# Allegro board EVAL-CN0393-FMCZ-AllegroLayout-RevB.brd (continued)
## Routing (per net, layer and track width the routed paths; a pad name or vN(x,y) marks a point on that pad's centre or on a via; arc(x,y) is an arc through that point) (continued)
VDD: length 13.1
  TOP w0.2: U1.19 28.75,16.12
  TOP w0.25: U2.20 28.25,44.25 28.75,44.25 U2.19 ; v1(28.75,16.88) 28.75,16.12 28.38,16.12 28.25,16 U1.20
  TOP w0.3: 28.75,44.25 v1(28.75,44.88)
  TOP w0.5: R54.1 v1(29.88,45.5) ; R53.1 v1(29.75,17.5) ; v1(28.75,44.88) C47.1 ; v1(28.75,16.88) C46.1
  LAYER3 w0.2: VDD.1 33.31,51.75 ; VDD.1 31.19,51.75 ; VDD.1 32.25,50.69 ; VDD.1 32.25,52.81
  BOTTOM w0.5: C30.1 v1(28.75,16.88) ; C31.1 v1(28.75,44.88)
VDD2: length 8
  TOP w0.3: C7.1 47.25,43.5 47.38,43.62 U6.18
  TOP w0.5: C12.2 v1(46.5,26.62) ; C7.1 v1(45.75,43.5)
  LAYER3 w0.2: VDD2.1 45.81,25 ; VDD2.1 44.75,23.94 ; VDD2.1 43.69,25 ; VDD2.1 44.75,26.06
  vias: v1(45.75,44) v1(47.62,27.62) v1(47.62,26.88) v1(48.38,27.62) v1(48.38,26.88)
VDDA: length 15.7
  TOP w0.37: v1(57.5,48.25) 57.5,47.95 57.08,47.52 U6.9
  TOP w1: v2(61.62,49.5) R35.2
  BOTTOM w0.5: v1(57.5,48.25) 58.75,49.5 v2(61.62,49.5)
  BOTTOM w1.5: v2(61.62,49.5) 61.62,50.96 60.5,52.08 VDDA.1
+ISO: length 5.9
  TOP w0.25: U6.20 48.69,41.68 ; 48.69,41.68 48.69,41.55 ; 48.69,41.68 v1(48.62,41.75)
  LAYER3 w0.2: UNK+ISO.1 39.81,65.25 ; UNK+ISO.1 38.75,64.19 ; UNK+ISO.1 38.75,66.31 ; UNK+ISO.1 37.69,65.25
  BOTTOM w0.5: v1(48.62,41.75) 48.75,41.88 R5.1
  vias: v1(48,41.75) v1(48,41) v1(48.75,41) v1(49.38,41.75) v1(49.38,41)
+VS: length 9.9
  TOP w0.25: C53.1 v1(15.5,45) A2.8 ; A1.8 v1(15.38,16.62) C52.1
  LAYER3 w0.2: UNK+VS.1 27.25,66.56 ; UNK+VS.1 27.25,64.44 ; UNK+VS.1 28.31,65.5 ; UNK+VS.1 26.19,65.5
  BOTTOM w0.25: C36.1 v1(15.5,45) ; C35.1 v1(15.38,16.62)
-ISO: length 4.8
  TOP w1: R8.2 UNK-ISO.1
  BOTTOM w1: R11.1 42.5,47.5 UNK-ISO.1
-VS: length 35.6
  TOP w0.25: C54.1 v1(15.38,9.88) A1.3 ; A2.6 16.95,43.67 ; C55.1 v1(15.5,38) A2.3 ; A1.6 16.83,15.55
  TOP w0.3: 16.83,15.55 v1(16.88,15.5) ; 16.95,43.67 v1(17,43.62)
  TOP w0.75: v2(36.5,34.62) 36.5,33.54 35.46,32.5 16.12,32.5 14.25,34.38 14.25,36.62 14.88,37.25 C55.1
  BOTTOM w0.25: C37.1 v1(15.38,9.88) ; C38.1 v1(15.5,38)
  BOTTOM w0.3: R22.1 36.5,33.85 v2(36.5,34.62)
AMP_OUTA: length 9.4
  TOP w0.25: U1.3 24.13,13.75 C65.2
  TOP w0.4: C65.2 23.53,13.15 RN1.8 ; 22.55,11.36 23.12,10.79 AMP_A.1 ; 22.55,11.36 22.5,11.41 v1(22.5,11.62) ; 22.55,11.36 RN1.8 ; RN1.8 RN1.7
  BOTTOM w0.4: CR1.3 22.38,11.75 v1(22.5,11.62)
AMP_OUTB: length 9.2
  TOP w0.25: C66.2 24.13,41.75 U2.3
  TOP w0.4: RN2.8 23.02,41.49 C66.2 ; RN2.8 22.68,40.24 22.88,40.04 v1(22.88,39.38) AMP_B.1 ; RN2.8 RN2.7
  BOTTOM w0.4: v1(22.88,39.38) 23.38,39.88 CR2.3
CA+: length 38.2
  TOP w0.4: R47.1 11,20.64 10.9,20.74 10.9,20.95 10.32,21.54 D6.2 8.7,21.54 8.66,21.5 CA+.1 J1.1
  BOTTOM w0.4: P2.3 9,45.17 9,30 8.5,29.5 8.5,27 7.5,26 CA+.1
CA-: length 37.5
  TOP w0.4: R48.1 10.75,8.86 D7.1 9.37,8.46 8.66,7.75 CA-.1 J2.1
  BOTTOM w0.4: P3.1 6.25,31.75 6.25,14.25 7.5,13 CA-.1
CB+: length 9.6
  TOP w0.4: J3.1 2.67,55.12 2.8,55.25 CB+.1 P2.1
CB-: length 9.6
  TOP w0.4: J4.1 6.21,41.38 6.34,41.5 CB-.1 P3.3
CNV: length 60.7
  TOP w0.2: U7.15 46.7,31.57 46.58,31.69 46.58,32.13 46.47,32.25 46.3,32.25 46.18,32.13 46.18,31.69 46.07,31.57 45.9,31.57 45.78,31.69 45.78,32.13 45.67,32.25 45.5,32.25 45.38,32.13 45.38,31.69 45.27,31.57 45.1,31.57 44.98,31.69 44.98,32.13 44.87,32.25 44.7,32.25 44.58,32.13 44.58,31.69 44.47,31.57 42.01,31.57 41.56,31.12 CNV.1 ; v1(32.12,12.25) 31.42,12.25 30.92,12.75 U1.13 ; U2.13 33.88,40.75 37.25,37.38 41.38,37.38 41.88,37.88 v1(41.88,39.25)
  BOTTOM w0.2: v1(32.12,12.25) 32.52,12.64 32.52,12.77 39,19.25 39,20.62 39.38,21 39.38,30 CNV.1 41.75,32.38 41.75,35 42.75,36 42.75,38.38 v1(41.88,39.25)
DCLK: length 23.2
  TOP w0.2: DCLK.1 64.5,24.75 61.75,24.75 61,25.5 61,30 57.47,33.52 U7.9
  BOTTOM w0.2: P1.H29 69.05,23.7 DCLK.1
G0A_ISO: length 73.5
  TOP w0.2: v1(41.54,6.71) 39.82,5 ADR0_A.1 38.5,5.25 ; U6.15 45.57,45.58 44.7,44.7 44.7,36.33 v1(42.75,34.38)
  TOP w0.25: A1.4 15.88,10.25 16,10.12 16,9.88 19,6.88 36.62,6.88 ADR0_A.1
  BOTTOM w0.2: v1(42.75,34.38) 42.36,33.98 42.36,10.11 41.54,9.29 v1(41.54,6.71)
G0B_ISO: length 44.3
  TOP w0.2: U6.13 45.67,46.88 43.8,45 43.8,38.17 42.12,36.5 34.25,36.5 ADR0_B.1 31.25,36 18.12,36 16.12,38 16.12,38.24 16,38.37 A2.4
G1A_ISO: length 69.6
  TOP w0.2: U6.16 45.55,44.92 45.12,44.5 45.12,35.5 v1(43.12,33.5) ; ADR1_A.1 v1(42.88,8.5)
  TOP w0.25: ADR1_A.1 37.62,7.62 19,7.62 16.5,10.12 16.5,10.38 16.38,10.5 A1.5
  BOTTOM w0.2: v1(43.12,33.5) 43.12,9.3 42.88,9.05 v1(42.88,8.5)
G1B_ISO: length 45.7
  TOP w0.2: v1(16.75,35.25) 17.75,34.25 ADR1_B.1 34.06,34.25 35.81,36 42.62,36 44.25,37.62 44.25,44.85 45.62,46.23 U6.14 ; v1(16.75,38.35) 16.5,38.6 A2.5
  BOTTOM w0.2: v1(16.75,35.25) v1(16.75,38.35)
GA0: length 21.2
  TOP w0.2: U19.1 67.47,5.09 68,5.62 68,9.38 69.5,10.88 69.5,11.5 69.75,11.75 70.38,11.75 74.12,15.5 75.38,15.5 77.25,17.38 v1(77.88,17.38)
  BOTTOM w0.2: P1.C34 77.19,17.38 v1(77.88,17.38)
GA1: length 16.8
  TOP w0.2: U19.2 66.86,6.37 67.5,7.01 67.5,9.75 69,11.25 69,11.75 69.75,12.5 70.38,12.5 74,16.12 v1(75.12,16.12)
  BOTTOM w0.2: P1.D35 75.86,16.12 v1(75.12,16.12)
GAIN_0A: length 17.6
  TOP w0.2: R46.1 v1(67.25,50.5) R44.1 ; U6.6 v1(57.08,45.58)
  BOTTOM w0.2: v1(57.08,45.58) 66.33,45.58 68.25,47.5 68.25,49.5 v1(67.25,50.5)
GAIN_0B: length 12.9
  TOP w0.2: R42.1 R40.1 66.75,48.24 v1(66.75,47.5) ; U6.8 v1(57.08,46.88)
  BOTTOM w0.2: v1(66.75,47.5) 66.12,46.88 v1(57.08,46.88)
GAIN_1A: length 19.8
  TOP w0.2: R45.1 v1(67.25,51.5) R43.2 ; U6.5 v1(57.5,44.92)
  BOTTOM w0.2: v1(67.25,51.5) 68.75,50 68.75,47.25 66.42,44.92 v1(57.5,44.92)
GAIN_1B: length 15.3
  TOP w0.2: R39.2 v1(67.25,49.25) R41.1 ; U6.7 v1(57.5,46.23)
  BOTTOM w0.2: v1(57.5,46.23) 66.35,46.23 67.75,47.62 67.75,48.75 v1(67.25,49.25)
IN_A: length 5.3
  TOP w0.4: IN_A.1 19.88,10.79 19.95,10.86 RN1.5 19.19,13.15 19.09,13.25 R51.2
IN_B: length 4.3
  TOP w0.4: R52.2 19.22,41.25 19.32,41.15 RN2.5 20.07,38.99 20,38.91 IN_B.1
MCLK: length 25
  TOP w0.2: U7.3 58.38,29.62 59,29 59,21.75 61.25,19.5 MCLK.1
  BOTTOM w0.2: MCLK.1 63.5,18.75 63.5,18.5 64.5,17.5 66.75,17.5 68.17,16.09 P1.H35
MISO: length 22.4
  TOP w0.2: MISO.1 61.69,23 60,24.69 60,29.5 58.58,30.93 U7.5
  BOTTOM w0.2: MISO.1 64.5,21.25 66.75,21.25 68.11,19.89 P1.H32
MOSI: length 24.2
  TOP w0.2: U7.4 58.47,30.27 59.5,29.25 59.5,22.75 60.75,21.5 63,21.5 65,19.5 MOSI.1
  BOTTOM w0.2: MOSI.1 68.39,17.36 P1.H34
MSS: length 22
  TOP w0.2: MSS.1 65,24.25 61.5,24.25 60.5,25.25 60.5,29.75 58.67,31.57 U7.6
  BOTTOM w0.2: MSS.1 68.08,21.16 P1.H31
Net_22: length 0
  BOTTOM w0.2: 77.17,32.59 77.2,32.62
REF_OUTA: length 3.5
  TOP w0.25: U1.24 26.25,15.7 25.8,15.7
  TOP w0.3: 25.8,15.7 v1(25.75,15.75)
  BOTTOM w0.3: v1(25.75,15.75) 25.12,15.12 25.06,15.12 25.05,15.12 24.3,15.12 24.17,14.99 CR1.2
REF_OUTB: length 2.6
  TOP w0.25: v1(25.8,43.8) 25.8,43.75 25.85,43.7 26.25,43.7 U2.24
  BOTTOM w0.25: v1(25.8,43.8) 25.12,43.12 24.56,43.12 CR2.2
SCK: length 61
  TOP w0.2: v1(38.12,38.62) 37.45,38.62 34.32,41.75 U2.15 ; v1(40.5,11.12) 39.75,11.12 37.12,13.75 U1.15 ; v1(38.25,26.75) SCK.1 43.25,27.25 43.25,28.5 44.75,30 47,30 47.38,29.62 U7.18
  BOTTOM w0.2: v1(38.12,38.62) 38.12,27.43 38.25,27.3 v1(38.25,26.75) ; v1(40.5,11.12) SCK.1
SDI_A: length 22.1
  TOP w0.2: v1(41.5,18.25) JP1.1 ; U7.17 47.47,30.27 47.25,30.5 44.31,30.5 41.56,27.75 SDIA.1
  BOTTOM w0.2: SDIA.1 41.75,26.5 41.75,19.18 41.5,18.93 v1(41.5,18.25)
SDO_A: length 34.7
  TOP w0.2: v1(38.75,39.62) 37.5,40.88 JP2.1 ; U1.14 31.33,13.25 31.38,13.2 v1(31.38,13.12)
  BOTTOM w0.2: v1(31.38,13.12) 37.5,19.25 SDOA.1 38.88,23.12 38.88,27 38.75,27.12 v1(38.75,39.62)
SDO_B: length 35.9
  TOP w0.2: U7.16 42.42,30.93 41.38,29.88 39.62,29.88 39.12,30.38 39.12,30.77 39.01,30.88 38.12,30.88 38,31 38,31.17 38.12,31.28 39.01,31.28 39.12,31.4 39.12,31.57 39.01,31.68 38.12,31.68 38,31.8 38,31.97 38.12,32.08 39.01,32.08 39.12,32.2 39.12,32.37 39.01,32.48 38.12,32.48 38,32.6 38,32.77 38.12,32.88 39.01,32.88 SDOB.1 ; U2.14 34.12,41.25 37.38,38 v1(39.88,38)
  BOTTOM w0.2: SDOB.1 40.5,35.75 39.88,36.38 v1(39.88,38)
UNNAMED_2_ADR45XX_I73_NC4: length 2
  TOP w0.75: U5.7 v1(14.88,55.62)
  BOTTOM w0.75: v1(14.88,55.62) 14.99,55.5 R2.1
UNNAMED_2_ADR45XX_I73_VOUT: length 3.4
  TOP w0.75: U5.6 14.76,56.88 v1(14.75,56.88) 13.88,56.88 R3.1
  BOTTOM w0.75: C5.1 15.12,57.25 v1(14.75,56.88)
UNNAMED_2_ADUM3470_I1_FB: length 3.2
  TOP w0.2: v1(47.5,44.25) 47.53,44.27 U6.17
  BOTTOM w0.5: 47.5,44 v1(47.5,44.25) ; 47.5,44 R5.2 ; 47.5,44 R6.1
UNNAMED_2_ADUM3470_I1_OC: length 2.8
  TOP w0.37: v1(47.12,47.62) 47.22,47.52 U6.12
  BOTTOM w0.37: v1(47.12,47.62) 48.12,47.62 R4.1
UNNAMED_2_ADUM3470_I1_X1: length 20.6
  TOP w0.37: U6.1 56.3,42.33 56.75,41.88 v1(56.75,41.75)
  TOP w0.5: v1(56.75,41.75) 56.97,41.97 57.72,41.97 58.38,42.62 v1(58.38,50.62)
  BOTTOM w0.5: v2(59.12,59.62) 58.38,58.88 v1(58.38,50.62)
  vias: v1(55.5,41.75) v1(55.5,41.12) v1(56.12,41.75) v1(56.12,41.12) v1(56.75,41.12)
UNNAMED_2_ADUM3470_I1_X2: length 13.1
  TOP w0.37: U6.4 56.97,44.27 v1(57.25,44)
  TOP w1: v1(59.62,44.25) 59.75,44.38 59.75,45.75 60,46 R55.1
  BOTTOM w0.5: v1(59.5,44.25) 59.25,44 v1(57.25,44)
UNNAMED_2_CAP_I27_N1: length 5.6
  TOP w1: L1.2 39.57,60.45 C9.1 39.5,62.25 R7.1
UNNAMED_2_CAP_I34_N2: length 5.6
  TOP w1: L2.2 39.57,52.55 C10.2 39.5,50.75 R8.1
UNNAMED_2_CAP_I84_N2: length 3.2
  BOTTOM w0.75: R2.2 17.75,55.5 17.75,57.25 C5.2
UNNAMED_2_CAP_I98_N1: length 1.8
  TOP w0.75: R55.2 C61.1
UNNAMED_2_CAP_I100_N1: length 1.8
  TOP w0.75: R56.2 C62.1
UNNAMED_2_DIOSCHOTTKY_I28_N: length 4.1
  TOP w1: v2(44.25,57) 43.75,57 43,57.75 L1.1
  BOTTOM w1: D1.C v2(44.25,57) D3.C
UNNAMED_2_DIOSCHOTTKY_I28_P: length 5.7
  TOP w1: T1.8 45.61,52.25 v2(45.5,52.25)
  BOTTOM w1: D2.C D1.A 45.36,52.11 v2(45.5,52.25)
UNNAMED_2_DIOSCHOTTKY_I29_P: length 4.1
  TOP w1: v2(41.75,56) 42.25,56 43,55.25 L2.1
  BOTTOM w1: D2.A v2(41.75,56) D4.A
UNNAMED_2_DIOSCHOTTKY_I30_P: length 5.7
  TOP w1: v2(45.5,60.75) 45.61,60.75 T1.5
  BOTTOM w1: D4.C D3.A 45.36,60.89 v2(45.5,60.75)
UNNAMED_2_RES_I92_N2: length 1.9
  TOP w0.4: RN3.8 22.4,23.18 22.48,23.25 R9.2
UNNAMED_2_RES_I96_N2: length 1.8
  TOP w0.4: R10.2 22.23,50.88 22.12,50.93 RN4.8
UNNAMED_2_RESNET8P4R_I87_N1: length 1.7
  TOP w0.4: RN3.3 RN3.2 RN3.1
UNNAMED_2_RESNET8P4R_I93_N1: length 1.7
  TOP w0.4: RN4.3 RN4.2 RN4.1
UNNAMED_3_ADP1614_I77_EN: length 10.4
  TOP w0.25: U4.3 v1(68.38,36.5)
  BOTTOM w0.25: v1(60.25,33) 62,34.75 66.38,34.75 67.72,36.09 67.97,36.09 v1(68.38,36.5)
UNNAMED_3_ADP1614_I77_FB: length 3.9
  TOP w0.25: U4.2 68,36 68.12,35.88 68.25,35.88 68.3,35.82 69.07,35.82 R31.2
  TOP w0.5: R31.2 R32.1
UNNAMED_3_CAP_I82_N1: length 16
  TOP w0.25: R32.2 v1(69.25,32.25)
  TOP w0.75: L4.2 R35.1
  BOTTOM w0.25: v1(69.25,32.25) 69.25,37.5 64.41,42.34 64.41,42.72 v1(64,43.12)
UNNAMED_3_CAP_I86_N2: length 1
  TOP w0.5: C32.2 68.24,33 R30.2
UNNAMED_3_CN2P_I157_N2: length 15.3
  TOP w0.75: R28.1 v1(62.75,25.75) ; P4.2 57.5,18.16 R29.1
  BOTTOM w0.75: v1(62.75,25.75) 61.25,25.75 60,24.5 60,20 58.75,18.75 P4.2
UNNAMED_3_DIOLED_I122_P: length 1.9
  TOP w0.5: R33.1 DS2.A
UNNAMED_3_DIOLED_I125_P: length 1.9
  TOP w0.5: R20.2 DS1.A
UNNAMED_4_CN160PCDGH_I2_N30: length 28.5
  TOP w0.2: v1(78,22.38) 78.84,21.54 78.84,19.84 78.25,19.25 77.38,19.25 74.88,16.75 72.25,16.75 71.75,16.25 71.75,15.5 68.5,12.25 68.5,11.5 66.75,9.75 63.5,9.75 61.39,7.63 U19.6
  BOTTOM w0.2: v1(78,22.38) 77.23,22.38 P1.C30
UNNAMED_4_CN160PCDGH_I2_N31: length 25.3
  TOP w0.2: v1(78,21.12) 77.45,21.12 73.57,17.25 71.25,17.25 68,14 68,11.75 66.5,10.25 63,10.25 61.66,8.9 U19.5
  BOTTOM w0.2: v1(78,21.12) 77.22,21.12 P1.C31
UNNAMED_4_CN160PCDGH_I3_N1: length 50.7
  TOP w0.75: v2(76.75,61.5) 77.83,61.5 81,58.33 81,17.07 80.75,16.82 R38.2
  BOTTOM w0.75: v2(76.75,61.5) 75.91,60.66 P1.D1
UNNAMED_4_CN160PCDGH_I3_N30: length 1.3
  BOTTOM w0.2: P1.D30 P1.D31
UNNAMED_4_CN160PCDGH_I4_N9: length 5.1
  TOP w0.2: v1(72.75,49.1) 72.2,49.1 71.55,49.75 69.84,49.75 69.34,49.25 R41.2
  BOTTOM w0.2: v1(72.75,49.1) 72.09,49.1
UNNAMED_4_CN160PCDGH_I4_N10: length 4.8
  TOP w0.2: R42.2 72.33,48.25 v1(72.75,47.84)
  BOTTOM w0.2: P1.G10 v1(72.75,47.84)
UNNAMED_4_CN160PCDGH_I5_N7: length 2.1
  TOP w0.25: v1(69.38,51.5) R45.2
  BOTTOM w0.25: v1(69.38,51.5) 69.95,51.5 70.1,51.65 P1.H7
UNNAMED_4_CN160PCDGH_I5_N8: length 2.2
  TOP w0.25: v1(69.38,50.5) R46.2
  BOTTOM w0.25: v1(69.38,50.5) 70.12,50.5 70.18,50.55 70.45,50.55 70.62,50.38 P1.H8
UNNAMED_4_ICM24CXX_I6_VCC: length 2.5
  TOP w0.2: R37.1 58.17,5 58.27,5.09 U19.8
UNNAMED_5_AD8251_I6_: length 5.1
  TOP w0.25: A1.10 14.05,15.55
  TOP w0.4: R47.2 C57.1 12.5,15.96 12.91,15.55 14.05,15.55
UNNAMED_5_AD8251_I6__1: length 4.7
  TOP w0.25: 14.12,11.88 14.38,11.62 A1.1
  TOP w0.4: 14.12,11.88 13.75,12.25 13.27,12.25 13.02,12 C58.1 R48.2
UNNAMED_5_AD8251_I6_OUT: length 3.7
  TOP w0.25: A1.7 15.88,14.56 16.19,14.25 17,14.25 17.5,14.75 R51.1
UNNAMED_5_AD8251_I180_: length 3.8
  TOP w0.25: A2.1 14.33,39.33 14.25,39.25 14,39.25
  TOP w0.4: R50.2 C60.1 14,39.25
UNNAMED_5_AD8251_I180__1: length 3.8
  TOP w0.25: 14.02,43.67 A2.10
  TOP w0.4: R49.2 C59.1 13.75,43.75 13.83,43.67 14.02,43.67
UNNAMED_5_AD8251_I180_OUT: length 3.5
  TOP w0.25: R52.1 17.5,42.75 17.25,42.5 16.19,42.5 16,42.69 A2.7
UNNAMED_5_ADAQ798X_I1_IN: length 6.2
  TOP w0.25: 21.77,14.85 RN1.2 ; 21.77,14.85 21.77,14.53 20.98,13.72 20.98,13.4 20.85,13.28 RN1.6 ; 21.77,14.85 RN1.1 ; C65.1 24.13,14.25 U1.2
  TOP w0.4: C65.1 23.53,14.85 RN1.1
UNNAMED_5_ADAQ798X_I1_SDI: length 9.8
  TOP w0.2: JP1.2 36.05,18.25 35.75,17.95 35.75,16.25 33.75,14.25 U1.16
UNNAMED_5_ADAQ798X_I184_IN: length 6.1
  TOP w0.25: U2.2 24.13,42.25 C66.1 ; RN2.2 21.77,42.4 20.98,41.6 RN2.6
  TOP w0.4: RN2.2 RN2.1 23.02,42.51 C66.1
UNNAMED_5_ADAQ798X_I184_SDI: length 8.5
  TOP w0.2: JP2.2 35.17,42.25 U2.16
UNNAMED_5_CN3P_I304_N2: length 5.7
  TOP w0.4: R49.1 11,46.39 10.9,46.49 10.9,46.7 10.32,47.29 D8.2 9.88,47.29 9.3,47.88 8.83,47.88 P2.2
UNNAMED_5_CN3P_I305_N2: length 5
  TOP w0.4: P3.2 8.73,35.54 8.89,35.71 D9.1 10.32,35.71 10.9,36.3 10.9,36.51 11,36.61 R50.1
UNNAMED_5_RESNET8P4R_I216_N1: length 0.9
  TOP w0.4: RN1.4 RN1.3
UNNAMED_5_RESNET8P4R_I220_N1: length 0.9
  TOP w0.4: RN2.3 RN2.4
V+: length 19.6
  TOP w0.25: v1(27.6,44.8) 27.75,44.65 U2.21 ; 27.62,16.88 27.75,16.75 v1(27.75,16.38) U1.21 ; U1.10 28.25,11.25 28.38,11.12 v1(28.75,11.12) U1.11 ; U2.10 28.25,39.25 28.38,39.12 v1(28.75,39.12) U2.11
  TOP w0.5: C41.1 27,45.4 v1(27.6,44.8) ; 27.62,16.88 C40.1
  BOTTOM w0.5: 27.6,48.48 27.61,48.49 ; C24.1 27.74,16.39 v1(27.75,16.38) ; 27.25,44.45 C25.1
  BOTTOM w0.75: 27.61,48.49 29.5,50.38 R26.2 ; 27.25,44.45 v1(27.6,44.8) 27.6,48.48
V-: length 10.2
  TOP w0.25: C44.1 v1(27.25,38.5) U2.8 ; U1.8 27.25,11
  TOP w0.5: C43.1 v1(27.25,10.38) 27.25,11
  LAYER3 w0.2: V-.1 26.75,27.19 ; V-.1 26.75,25.06 ; V-.1 25.69,26.12 ; V-.1 27.81,26.12
  BOTTOM w0.25: C27.1 v1(27.25,38.5)
  BOTTOM w0.5: v1(27.25,10.38) C26.1
VBIAS_A: length 10.2
  TOP w0.25: U1.1 25.25,14.75 24.88,15.12
  TOP w0.4: RN3.7 RN3.6 RN3.5 21.35,19.19 21.38,19.16 VB_A.1 22.76,16.62 C63.1 24.88,15.74 24.88,15.12
VBIAS_B: length 10.5
  TOP w0.25: 25.3,43.23 25.3,42.75 U2.1
  TOP w0.4: 25.3,43.23 25.02,43.23 23.88,44.38 C64.1 23.17,45.12 22.41,45.88 VB_B.1 21.23,47.57 RN4.5 RN4.6 RN4.7
VIO: length 29.6
  TOP w0.2: U1.17 30.2,14.75
  TOP w0.25: 30.2,14.75 30.62,14.75 v1(30.88,15) ; U2.17 30.9,42.75 v1(31,42.85) 31.05,42.85 31.2,43 C50.1
  TOP w0.5: R54.2 34.62,47 35.62,46 35.62,44.61 JP2.3 35.59,44.53 34.07,43 C50.1 ; R53.2 VIO.1 33.25,17.75 33.62,17.38 33.62,15.53 33.1,15 C49.1 v1(30.88,15)
  LAYER3 w0.2: VIO.1 33.25,20.06 ; VIO.1 32.19,19 ; VIO.1 33.25,17.94 ; VIO.1 34.31,19
  BOTTOM w0.25: C34.1 30.63,43.12 30.9,42.85 v1(31,42.85)
  BOTTOM w0.5: v1(30.88,15) 30.76,15.12 C33.1
VREF: length 33.9
  TOP w0.25: U2.23 26.75,44.45 26.7,44.5 ; U1.23 26.75,16.38 26.5,16.62
  TOP w0.5: 26.7,44.5 26.62,44.5 26.5,44.62 v1(25.5,44.62) ; 26.5,16.62 26.33,16.62 26.2,16.75 26,16.75
  TOP w0.75: R9.1 24.75,19.38 25.38,18.75 v1(25.38,17.38) 26,16.75 ; R3.2 C6.1 13.75,53.12 14.26,52.62 14.26,51.56 C8.1 VREF.1 17.82,52.45 23.68,52.45 24.5,51.62 R10.1 24.5,49.5 25.5,48.5 v1(25.5,44.62)

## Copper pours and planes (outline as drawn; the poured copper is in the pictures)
+3.3V_SDP on LAYER3: 56.75,15.75 58.75,17.75 68.25,17.75 70.5,15.5 81.75,15.5 81.75,8.25 72.75,8.25 72,9 62.5,9 56.75,14.75
AGND on TOP (solid shape): 49.62,35.88 48.75,35.88 48.75,40.12 49.62,40.12
AGND on TOP (solid shape): 49.5,35.75 49.5,34 47.12,34 47.12,35.75 47.38,36 49.25,36
AGND on TOP (solid shape): 49.5,49.88 49.5,48 47.5,48 46.88,48.62 46.88,49.88 47,50 49.38,50
AGND on TOP (solid shape): 27.62,59.38 27.62,56.75 27.5,56.62 22.88,56.62 22.88,57.5 22.62,57.75 19.75,57.75 19.75,59.5 27.5,59.5
AGND on TOP (solid shape): 47.38,29.12 49.5,29.12 49.5,28.88 47.75,28.88 47,28.12 45,28.12 45,29.5 45.12,29.62 46.88,29.62
AGND on TOP (solid shape): 49,42.88 47.72,42.88 47.4,42.55 47.4,40.77 47.38,40.75 45.62,40.75 45.5,40.88 45.5,42.75 47.1,42.75 47.4,43.05 49,43.05
AGND on TOP (solid shape): 34.88,64.88 35.4,64.35 35.4,60.62 33.6,60.62 33.6,62.75 34.38,62.75 34.62,63 34.62,64.38 34.38,64.62 31.25,64.62 31.12,64.75 31.12,67.25 34.88,67.25
AGND on TOP (solid shape): 40.75,54.25 40.5,54 38.75,54 37.88,53.12 37.25,53.12 37.25,54.5 37.12,54.62 35.88,54.62 35.5,54.25 35.5,52 35.38,51.88 34,51.88 33.62,52.25 33.62,54.5 34.12,55 35.25,55 35.62,55.38 37.62,55.38 38.05,55.8 38.05,58.55 38.25,58.75 40.75,58.75
AGND on BOTTOM (solid shape): 37.75,27.12 36.75,27.12 36.62,27.25 36.62,28.62 37.12,29.12 37.75,29.12
AGND on BOTTOM (solid shape): 40.75,43.12 40.12,42.5 37.75,42.5 37.5,42.75 37.5,44.25 37.62,44.38 40.75,44.38
AGND on BOTTOM (solid shape): 35.25,28.95 35.1,28.8 35.1,28 34.9,28 34.9,28.73 34.58,29.05 33.08,29.05 32.5,29.62 32.5,31.12 33,31.62 35.25,31.62
AGND on BOTTOM (solid shape): 41.5,49.88 41.38,49.75 41.38,48.5 41.62,48.25 41.62,46.62 41.5,46.5 39.62,46.5 38,48.12 38,50.25 38.12,50.38 41.5,50.38
AGND on BOTTOM (solid shape): 30.88,56.5 30.62,56.25 28.25,56.25 28.25,57.7 28.08,57.88 26.75,57.88 26.45,57.58 26.45,56.75 25.88,56.75 25.88,57.62 25.6,57.9 24.38,57.9 24.38,59.12 24.5,59.25 25.4,59.25 26.02,58.62 28.2,58.62 28.2,59.83 28.38,60 30.88,60
AGND on TOP: 0.25,0.5 0.25,68.75 49.62,68.75 49.62,0.5 ; 2 cut-outs
AGND on BOTTOM, LAYER3: 0.25,0.5 0.25,68.75 49.62,68.75 49.62,0.5
AGND on LAYER2: 0.25,0.5 0.25,68.75 49.62,68.75 49.62,0.5
DGND on TOP (solid shape): 56,35.62 55,35.62 54.88,35.75 54.88,40.12 56,40.12
DGND on TOP (solid shape): 57,48.38 56.62,48 55,48 54.88,48.12 54.88,49.88 55,50 57,50
DGND on TOP (solid shape): 57.25,36 57.25,34.25 57,34 55,34 54.88,34.12 54.88,36 55.12,36.25 57,36.25
DGND on TOP (solid shape): 58.5,28.75 58.5,28.5 57.21,28.5 57.12,28.62 56.88,28.88 55,28.88 55,29.12 57.12,29.12 57.25,29.25 58,29.25
DGND on TOP (solid shape): 67.88,45.5 67.88,41.5 70.25,39.12 70.25,37.12 68,37.12 67.88,37 67,37 66.62,36.62 66.62,32.62 67.12,32.12 67.12,29.12 66.62,28.62 64.25,28.62 64,28.88 64,33 64.12,33 64.62,33.5 64.62,34.38 65.25,35 65.25,38.5 65,38.75 65,46.12 67.25,46.12
DGND on TOP, BOTTOM, LAYER3: 54.88,0.5 54.88,68.75 82.5,68.75 82.5,0.5
DGND on LAYER2: 54.88,0.5 54.88,68.75 82.5,68.75 82.5,0.5
VDD on TOP (solid shape): 34,51.5 37.25,51.5 37.25,50.38 37.12,50.25 31.5,50.25 31.25,50.5 31.25,52.25 31.62,52.62 32.88,52.62
VDD on LAYER3: 30.25,16.12 29,16.12 28.5,16.62 28.5,17.38 30,18.88 30,38.81 29.25,39.38 29.25,43.12 28.25,44.12 28.25,51 30.38,53.12 33.5,53.12 33.75,52.75 33.75,50.75 30.75,47.75 30.75,16.62
VDD1 on TOP (solid shape): 56.62,27.88 57,27.5 58.25,27.5 58.5,27.25 58.5,20.75 56.88,20.75 56.25,21.38 56.25,25 55.25,26 55.25,28.38 56.62,28.38
VDD2 on TOP (solid shape): 49.5,26.25 48.75,25.5 46,25.5 45.62,25.88 45.62,27.62 47.12,27.62 47.88,28.38 49.5,28.38
VDD2 on TOP (solid shape): 47.1,43.7 49.12,43.7 49.12,43.5 47.45,43.5 47.08,43.12 45.62,43.12 45.5,43.25 45.5,44.25 46.55,44.25
VDD2 on LAYER3: 46.38,44.62 45.5,44.62 45.12,44.25 45.12,42 43.38,40.25 43.38,27.5 43,27.12 43,24 44,23 46.5,23 48.5,25 48.5,27.75 46.88,29.38 46.88,39.62 46.38,40.12
VDDA on TOP (solid shape): 63.75,54.75 57,54.75 57,58.25 63.75,58.25
+ISO on TOP (solid shape): 49.62,40.88 49.5,40.75 47.88,40.75 47.75,40.88 47.75,42.25 48,42.5 49.62,42.5
+ISO on TOP (solid shape): 41.5,65.62 41.5,65 40.38,63.88 38.62,63.88 38.12,63.38 38.12,62 35.88,62 35.85,62.02 35.85,62.65 36.48,62.65 36.49,62.64 36.85,63 36.85,63.6 36.7,63.75 35.9,63.75 35.9,64.7 35.46,65.14 35.57,66.7 40.38,66.75
+ISO on LAYER3: 37.62,66.88 37.62,64.38 37.5,64.25 37.5,62.88 41,59.38 41,51.62 47.12,45.5 47.12,40.75 47.62,40.25 49.62,40.25 49.62,46.5 43.62,52.5 43.62,61.88 40.25,65.25 40.25,66.38 39.75,66.88
+VS on TOP (solid shape): 30.62,66.62 30.62,64.5 31,64.12 31.38,64.12 31.38,63.38 31.25,63.25 27.12,63.25 26.38,64 26.38,66.38 26.75,66.75 30.5,66.75
+VS on BOTTOM (solid shape): 28.25,66 28.25,63.88 27.75,63.38 26.75,63.38 25.75,64.38 25.75,66 26.25,66.5 27.75,66.5
+VS on LAYER3: 28.62,67.12 26.5,67.12 12.88,53.5 12.88,17.12 13.88,16.12 15.75,16.12 16.62,17 16.62,33.38 14.5,35.5 14.5,42.75 17.12,45.38 17.12,49 15.88,50.25 15.88,52.38 28.88,65.38 29,65.38 29,66.75
-VS on BOTTOM (solid shape): 43.5,42.25 43.5,40.88 43.12,40.5 37.62,40.5 37,39.88 37,33.25 35.88,33.25 35.88,42.38 36,42.5 37.25,42.5 37.5,42.25 40.25,42.25 40.62,42.62 43.12,42.62
-VS on LAYER3: 18.75,44.25 17.25,44.25 16.25,43.25 16.25,40.38 15.38,39.5 15.38,36.12 17.25,34.25 17.25,16.38 16.38,15.5 16.38,11.75 14.88,10.25 14.88,9.5 15.38,9 17.25,9 19,10.75 19,44
UNNAMED_2_ADR45XX_I73_VIN on TOP (solid shape): 28.62,55.88 28.62,54.75 28.25,54.38 23.25,54.38 22.5,55.12 20.38,55.12 20.25,55.25 20.25,56.12 28.38,56.12
UNNAMED_2_ADUM3470_I1_X1 on TOP (solid shape): 60.75,59.25 60.25,58.75 56.75,58.75 56.75,60.25 60.75,60.25
UNNAMED_2_ADUM3470_I1_X1 on TOP (solid shape): 59,42.5 59,41.38 58.38,40.75 55.12,40.75 55,40.88 55,42.5 56.75,42.5 57,42.25 57.62,42.25 58.12,42.75 58.75,42.75
UNNAMED_2_ADUM3470_I1_X2 on TOP (solid shape): 59.75,53.75 60.5,53.75 60.5,52.75 60.25,52.5 57,52.5 56.75,52.75 56.75,54.25 59.25,54.25
UNNAMED_3_ADP1614_I77_CLRES on TOP (solid shape): 64.88,36 64.12,36 63.38,35.25 63.38,33.5 63.62,33.25 63.62,31.62 61.75,31.62 61.62,31.75 61.62,35.12 63,36.5 64.88,36.5
UNNAMED_3_ADP1614_I77_COMP on TOP (solid shape): 68.5,35 68.5,33.75 67.25,33.75 67.12,33.88 67.12,35.5 68,35.5
UNNAMED_3_ADP1614_I77_EN on TOP (solid shape): 61.25,31.62 61.5,31.38 63.5,31.38 63.5,27.5 62,27.5 62,29.5 59.25,32.25 59.25,34.12 61.25,34.12
UNNAMED_3_ADP1614_I77_SS on TOP (solid shape): 64.88,35.25 64.38,34.75 64.38,33.88 64.25,33.75 63.62,33.75 63.62,35.12 64,35.5 64.88,35.5
UNNAMED_3_ADP1614_I77_SW1 on TOP (solid shape): 62.62,38.38 64.88,38.38 64.88,37 63.12,37 61.5,35.38 59.25,35.38 59.25,37.25 60.62,38.62 62.38,38.62
UNNAMED_3_ADP7118_I9_EN on TOP (solid shape): 37.75,57.62 37.75,56 37.5,55.75 37.25,55.75 37.25,56.7 37.15,56.8 36.3,56.8 36.2,56.7 36.2,55.75 34.75,55.75 34.38,55.38 34.38,58.25 34.5,58.38 37,58.38
UNNAMED_3_ADP7118_I9_SENSE on TOP (solid shape): 36.88,53.38 37,53.25 37,52.25 36.88,52.12 36.12,52.12 35.75,52.5 35.75,54.12 35.88,54.25 36.88,54.25
UNNAMED_3_ADP7118_I18_EN on BOTTOM (solid shape): 30.25,62.25 30.25,60.62 28.25,60.62 27.95,60.33 27.95,59.08 27.88,59 27.5,59 27.5,59.75 27.2,60.05 26.67,60.05 26.5,59.88 26.5,59 26.12,59 25.88,59.25 25.88,61.75 26.75,62.62 29.88,62.62
UNNAMED_3_ADP7118_I18_SENSE on BOTTOM (solid shape): 25.62,57.38 25.62,56.62 25.8,56.45 26.6,56.45 26.88,56.73 26.88,57.5 27.12,57.5 27.12,56.67 26.75,56.3 26.75,55.5 26.5,55.25 25.12,55.25 24.88,55.5 24.88,57.5 25.5,57.5
UNNAMED_3_ADP7118_I18_VOUT on BOTTOM (solid shape): 27.95,54.55 28.38,54.12 28.38,52.88 28.25,52.75 27.5,52.75 27,53.25 27,56.12 27.5,56.62 27.5,57.5 27.95,57.5
UNNAMED_3_ADP7118_I24_SENSE on TOP (solid shape): 34.25,63.12 33.52,63.12 33,62.6 33,60.88 32.38,60.88 32.5,61 32.5,62.55 33.35,63.4 34.25,63.4
UNNAMED_3_ADP7118_I24_VOUT on TOP (solid shape): 34.15,63.85 33.05,63.85 32.12,62.92 32.12,62 32,61.88 31.5,61.88 31.38,62 31.38,62.88 32,63.5 32,64.25 32.12,64.38 34.15,64.38
UNNAMED_3_ADP7182V5_I43_ADJ on BOTTOM (solid shape): 37.62,48.88 35.7,46.95 35.7,46.25 36,45.95 36.75,45.95 36.75,45.62 35.83,45.62 35.58,45.88 34.62,45.88 34.5,46 34.5,49.5 34.88,49.88 37.62,49.88
UNNAMED_3_ADP7182V5_I43_EN on BOTTOM (solid shape): 37.9,46.85 37.9,45.25 39.75,45.25 39.88,45.38 39.88,46.25 43.38,46.25 43.38,44.88 43.12,44.62 37.1,44.62 37.1,46.02 36.83,46.3 36.1,46.3 36.1,46.85 36.25,47 37.75,47
UNNAMED_3_ADP7182V5_I43_VOUT on BOTTOM (solid shape): 35.65,45.25 36.75,45.25 36.75,44.38 37,44.12 37,43.12 36.88,43 33.12,43 32.62,43.5 32.62,45.5 32.67,45.55 35.35,45.55
UNNAMED_3_ADP7182V6_I29_EN on BOTTOM (solid shape): 37,32.62 37,29.38 36.25,28.62 36.25,27.12 36,26.88 34.75,26.88 34.5,26.62 34.5,25.88 34.38,25.75 33.88,25.75 33.75,25.88 33.75,27.5 33.88,27.62 35.6,27.62 35.6,31.48 35.75,31.62 35.75,32.5 36,32.75 36.88,32.75
UNNAMED_3_ADP7182V6_I29_VOUT on BOTTOM (solid shape): 37.5,24.5 37,24 35.12,24 35.12,25.25 35.6,25.73 35.6,26.4 36.15,26.4 36.38,26.62 37.5,26.62
UNNAMED_3_CAP_I82_N1 on TOP (solid shape): 64.62,46.62 64.62,41.25 64.5,41.12 63.5,41.12 63.38,41.25 63.38,43.25 62.5,44.12 60.88,44.12 60.75,44.25 60.75,47.25 64,47.25
UNNAMED_3_CAP_I96_N1 on TOP (solid shape): 62.88,43 62.88,41 63.38,40.5 64.62,40.5 64.62,38.75 63,38.75 62.62,39.12 60.62,39.12 60.5,39.25 60.5,43.12 60.75,43.38 62.5,43.38
UNNAMED_3_CAP_I98_N1 on BOTTOM (solid shape): 33.88,46.62 33.62,46.38 32.75,46.38 32.38,46.75 32.38,49.38 32.5,49.5 33.88,49.5
V+ on TOP (solid shape): 33.75,58.25 33.75,55.25 33,54.5 29.62,54.5 29.25,54.88 29.25,55.62 29.5,55.88 30.75,55.88 32.62,57.75 32.62,58.25 32.75,58.38 33.62,58.38
V+ on BOTTOM (solid shape): 33,55.62 33,54.75 31,52.75 29.12,52.75 29,52.88 29,54 28.5,54.5 28.5,55.88 28.62,56 32.62,56
V+ on LAYER3: 29.38,10.5 28.38,10.5 27.88,11 27.88,13.38 27.25,14 27.25,20.75 28.12,21.62 28.12,40.25 26.75,41.62 26.75,45 27.25,45.5 27.88,45.5 28.12,45.25 28.12,43.75 29.5,42.38 29.5,18.88 28.38,17.75 28.38,16.12 29.62,14.88 29.62,10.75
V- on BOTTOM (solid shape): 33.62,25.12 34.25,25.12 34.38,25 34.38,24.12 34.12,23.88 26.75,23.88 24.88,25.75 24.88,27 25.75,27.88 30.88,27.88
V- on LAYER3: 27,39 26.62,38.62 26.62,33.88 25.38,32.62 25.38,18.88 26.25,18 26.25,10 27.62,10 27.62,13.12 27,13.75 27,20.84 28.12,22.05 28.12,39
VIO on LAYER3: 30.62,43.5 30.5,43.25 30.5,42.62 31.62,41.5 31.62,16.29 30.51,15.1 30.5,14.38 30.75,14.12 31.88,14.12 34.5,16.75 34.5,40.5 31.5,43.5
VREF on LAYER3: 23.62,44.38 24.88,45.62 25.88,45.62 25.88,39.88 25.5,39.5 25.5,35.8 24.62,34.81 24.62,18.62 25.62,17.62 25.62,16.5 24,16.5 23.12,17.38 23.12,35.62 23.62,36.12

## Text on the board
User.Comments: CR_AIN_1
Ref Des/Silkscreen Top: 08-042443 Rev-B | EVAL-CN0393-FMCZ
LAYER2: 08-      -07 | L2 Internal GND
LAYER3: 08-      -08 | L3 Internal PWR
User.19: CN0393
User.22: 10. Manufacturer UL and Date codes on the bottom side silkscreen as indicated. | 7. SCREENING: Screen component outlines and nomenclature using indelible white ink on both sides. | 8. Electrically test 100%. | 9. Break all sharp edges 0.35mm Radius max. | 1. Material: 4 Layer FR4 glass epoxy laminate 1.6mm +/- 10%. material to be RoHS compliant. | 2. Plated thru holes and conductive pattern electroplated with 0.255mm min. thick copper. | 3. Processing tolerence: | 4. Warp and twist within 0.1875mm per 25mm (0.75%) | 5. Dimensions are for the finished part. | 6. SOLDERMASK: liquid Photo Imeagable soldermask over bare copper (SMOBC), | FABRICATION NOTES: | Nomenclature shall be legible. Screen to etch registration within 0.15mm total. | Board to be fabricated per IPC-6012A, CLASS 2. | Terminal areas and plated thru holes to be ENIG plated. | A. Conductive pattern front to back registration within 0.125mm total. | B. Minimum annual ring surrounding holes 0.05mm. | C. Finished conductive pattern to be within 0.05mm of true size. | D. Minimumfeature size 0.2mm | E. Minimum air gap 0.12mm | colour GREEN both sides using the pattern provided. No mask is permitted on the terminal areas. | Soldermask to etch registration within 0.125mm total. | 1 | FABRICATION | 09-042443-01 | B
User.23: FIGURE | SIZE | 0.254 | 0.4064 | 0.508 | 1.016 | 1.143 | 1.27 | 2.667 | DRILL CHART: TOP to BOTTOM | ALL UNITS ARE IN MILLIMETERS | PLATED | NON-PLATED | QTY | 516 | 64 | 8 | 46 | 2 | 4
